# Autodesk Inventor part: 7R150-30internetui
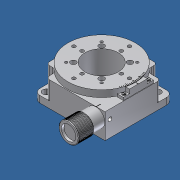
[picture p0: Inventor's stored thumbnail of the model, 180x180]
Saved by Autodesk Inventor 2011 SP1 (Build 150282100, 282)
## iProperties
Created: 2011-11
Part Number: 7R150-30internetui
Document SubType Name: Modeling
Designer: Darius
Density: 1 g/cm^3
Author: Darius
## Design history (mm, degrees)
feature "Base1"
body "Solid1"
